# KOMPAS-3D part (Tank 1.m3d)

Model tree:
1. Plane XY
2. Plane ZX
3. Plane ZY
4. X Axis
5. Y Axis
6. Z Axis
7. Origin
8. Sketch:1
9. Extrude:1
     Толщина стенки 1 = 1; Толщина стенки 2 = 1; Расстояние 1 = 1600; Расстояние 2 = 10
10. Fillet:1
11. Fillet:3
     Радиус = 300
12. Sketch:2  (labels: Емкость 1)
13. Revolve:1
     Толщина стенки 1 = 1; Толщина стенки 2 = 1; Угол 1 = 10; Угол 2 = 10
14. Sketch:4
15. Revolve:2
     Толщина стенки 1 = 1; Толщина стенки 2 = 1; Угол 1 = 1; Угол 2 = 1
16. Circular Pattern:1  (labels: Экземпляр ( 1, 2 );)
17. Операция вращения:1
18. Операция вращения:2  (with: Операция вращения:1)  (labels: Экземпляр ( 1, 3 );)
     N 1 = 1; Шаг 1 = 10; N 2 = 3; Шаг 2 = 360
19. Sketch:5
20. Extrude:2
     Толщина стенки 1 = 1; Толщина стенки 2 = 1; Расстояние 1 = 50; Расстояние 2 = 10
21. Sketch:6
22. Extrude:3
     Толщина стенки 1 = 1; Толщина стенки 2 = 1; Расстояние 1 = 100; Расстояние 2 = 341.477
23. Sketch:7
24. Extrude:4
     Толщина стенки 1 = 1; Толщина стенки 2 = 1; Расстояние 1 = 120; Расстояние 2 = 310.366
25. Path Pattern:1  (labels: Экземпляр ( 2 );)
26. Операция выдавливания:4
     Шаг = 430
27. Path Pattern:2  (with: Операция выдавливания:4)  (labels: Экземпляр ( 2 );)
     Шаг = 430
28. Sketch:8
29. Extrude:5
     Толщина стенки 1 = 1; Толщина стенки 2 = 1; Расстояние 1 = 100; Расстояние 2 = 10
30. Circular Pattern:2  (labels: Экземпляр ( 1, 2 );)
31. Операция выдавливания:5  (labels: Экземпляр ( 1, 3 );; C:\Program Files\ASCON\KOMPAS-3D V10\Sys\graphic.lyt; T.001; Tank 1)
     N 1 = 1; Шаг 1 = 10; N 2 = 3; Шаг 2 = 360

Referenced files in C:\Documents and Settings\kashirsky\Мои документы\Camtasia Studio\Pipelines3D\Tanks\: Capacity_1.a3d, Tank 1.m3d, Tank 1.a3d, Tank 1.spw
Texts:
  Tank 1
  Steel ASTM A295
  Three Point Plane
  Plane at Angle
  Line and Point Plane
  Axis through Two Vertices
  Axis of Feature
  Axis of Conical Surface
  Axis through Edge
  Приклеить элемент выдавливания
  Приклеить элемент вращения
  Приклеить кинематический элемент
  Приклеить элемент по сечениям
  Trim by Surface
  Trim by Sketch
  Feature with No History
  Intersection Axis of Two Planes
  Two Line Plane
  Line and Face Plane
  Bend by line
  Hole in sheet body
  Cut in sheet body
  Point in CM
  Linear Dimension from Line to Point
  Surface Finish Symbol
  Geometric Tolerance Symbol
  Текст на чертеже
  Линия-выноска #1
  Линия-выноска #2
  Линия-выноска #3
  Отклонения формы и база
  Марка координационной оси
  Марка/позиционное обозначение с линией-выноской
  Марка/позиционное обозначение на линии
  Марка/позиционное обозначение без линии-выноски
  Емкость 1
  Экземпляр ( 1, 2 );
  Экземпляр ( 1, 3 );
  Экземпляр ( 2 );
